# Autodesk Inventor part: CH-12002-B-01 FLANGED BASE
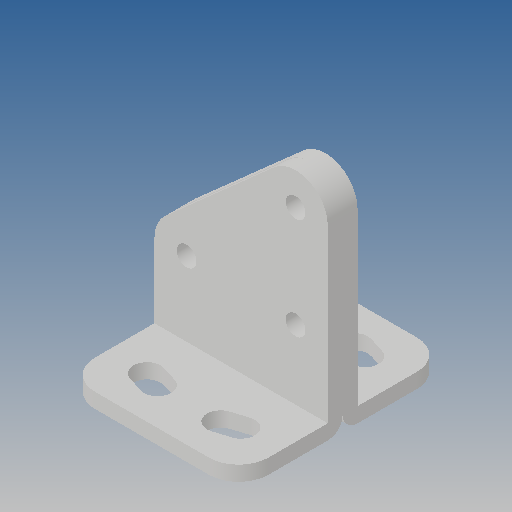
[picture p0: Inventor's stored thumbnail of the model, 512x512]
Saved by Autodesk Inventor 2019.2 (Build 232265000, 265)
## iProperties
Created: 2012-09
Part Number: CH-12002-B-01 FLANGED BASE
Material: Ogólny
Document SubType Name: Modeling
Designer: CADENGINEERING4
Density: 1 g/cm^3
Appearance: Domyślna
Author: CADENGINEERING4
Revision Number: ÈÎºÎ
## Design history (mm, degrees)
feature "ÇÐ³ý-À­Éì1"
feature "¾µÏò1"
node "Bryła1"
node "Bryła2"
